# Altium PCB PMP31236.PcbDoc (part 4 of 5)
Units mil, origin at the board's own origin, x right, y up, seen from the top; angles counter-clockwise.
Board outline 6425 x 5322.16 mil, 6 copper layers (Top Layer, Power / GND 1, Signal Layer 1, Signal Layer 2, Power / GND 2, Bottom Layer), stack 78.712 mil thick; 732 components, 346 nets, 1735 pads, 719 vias.
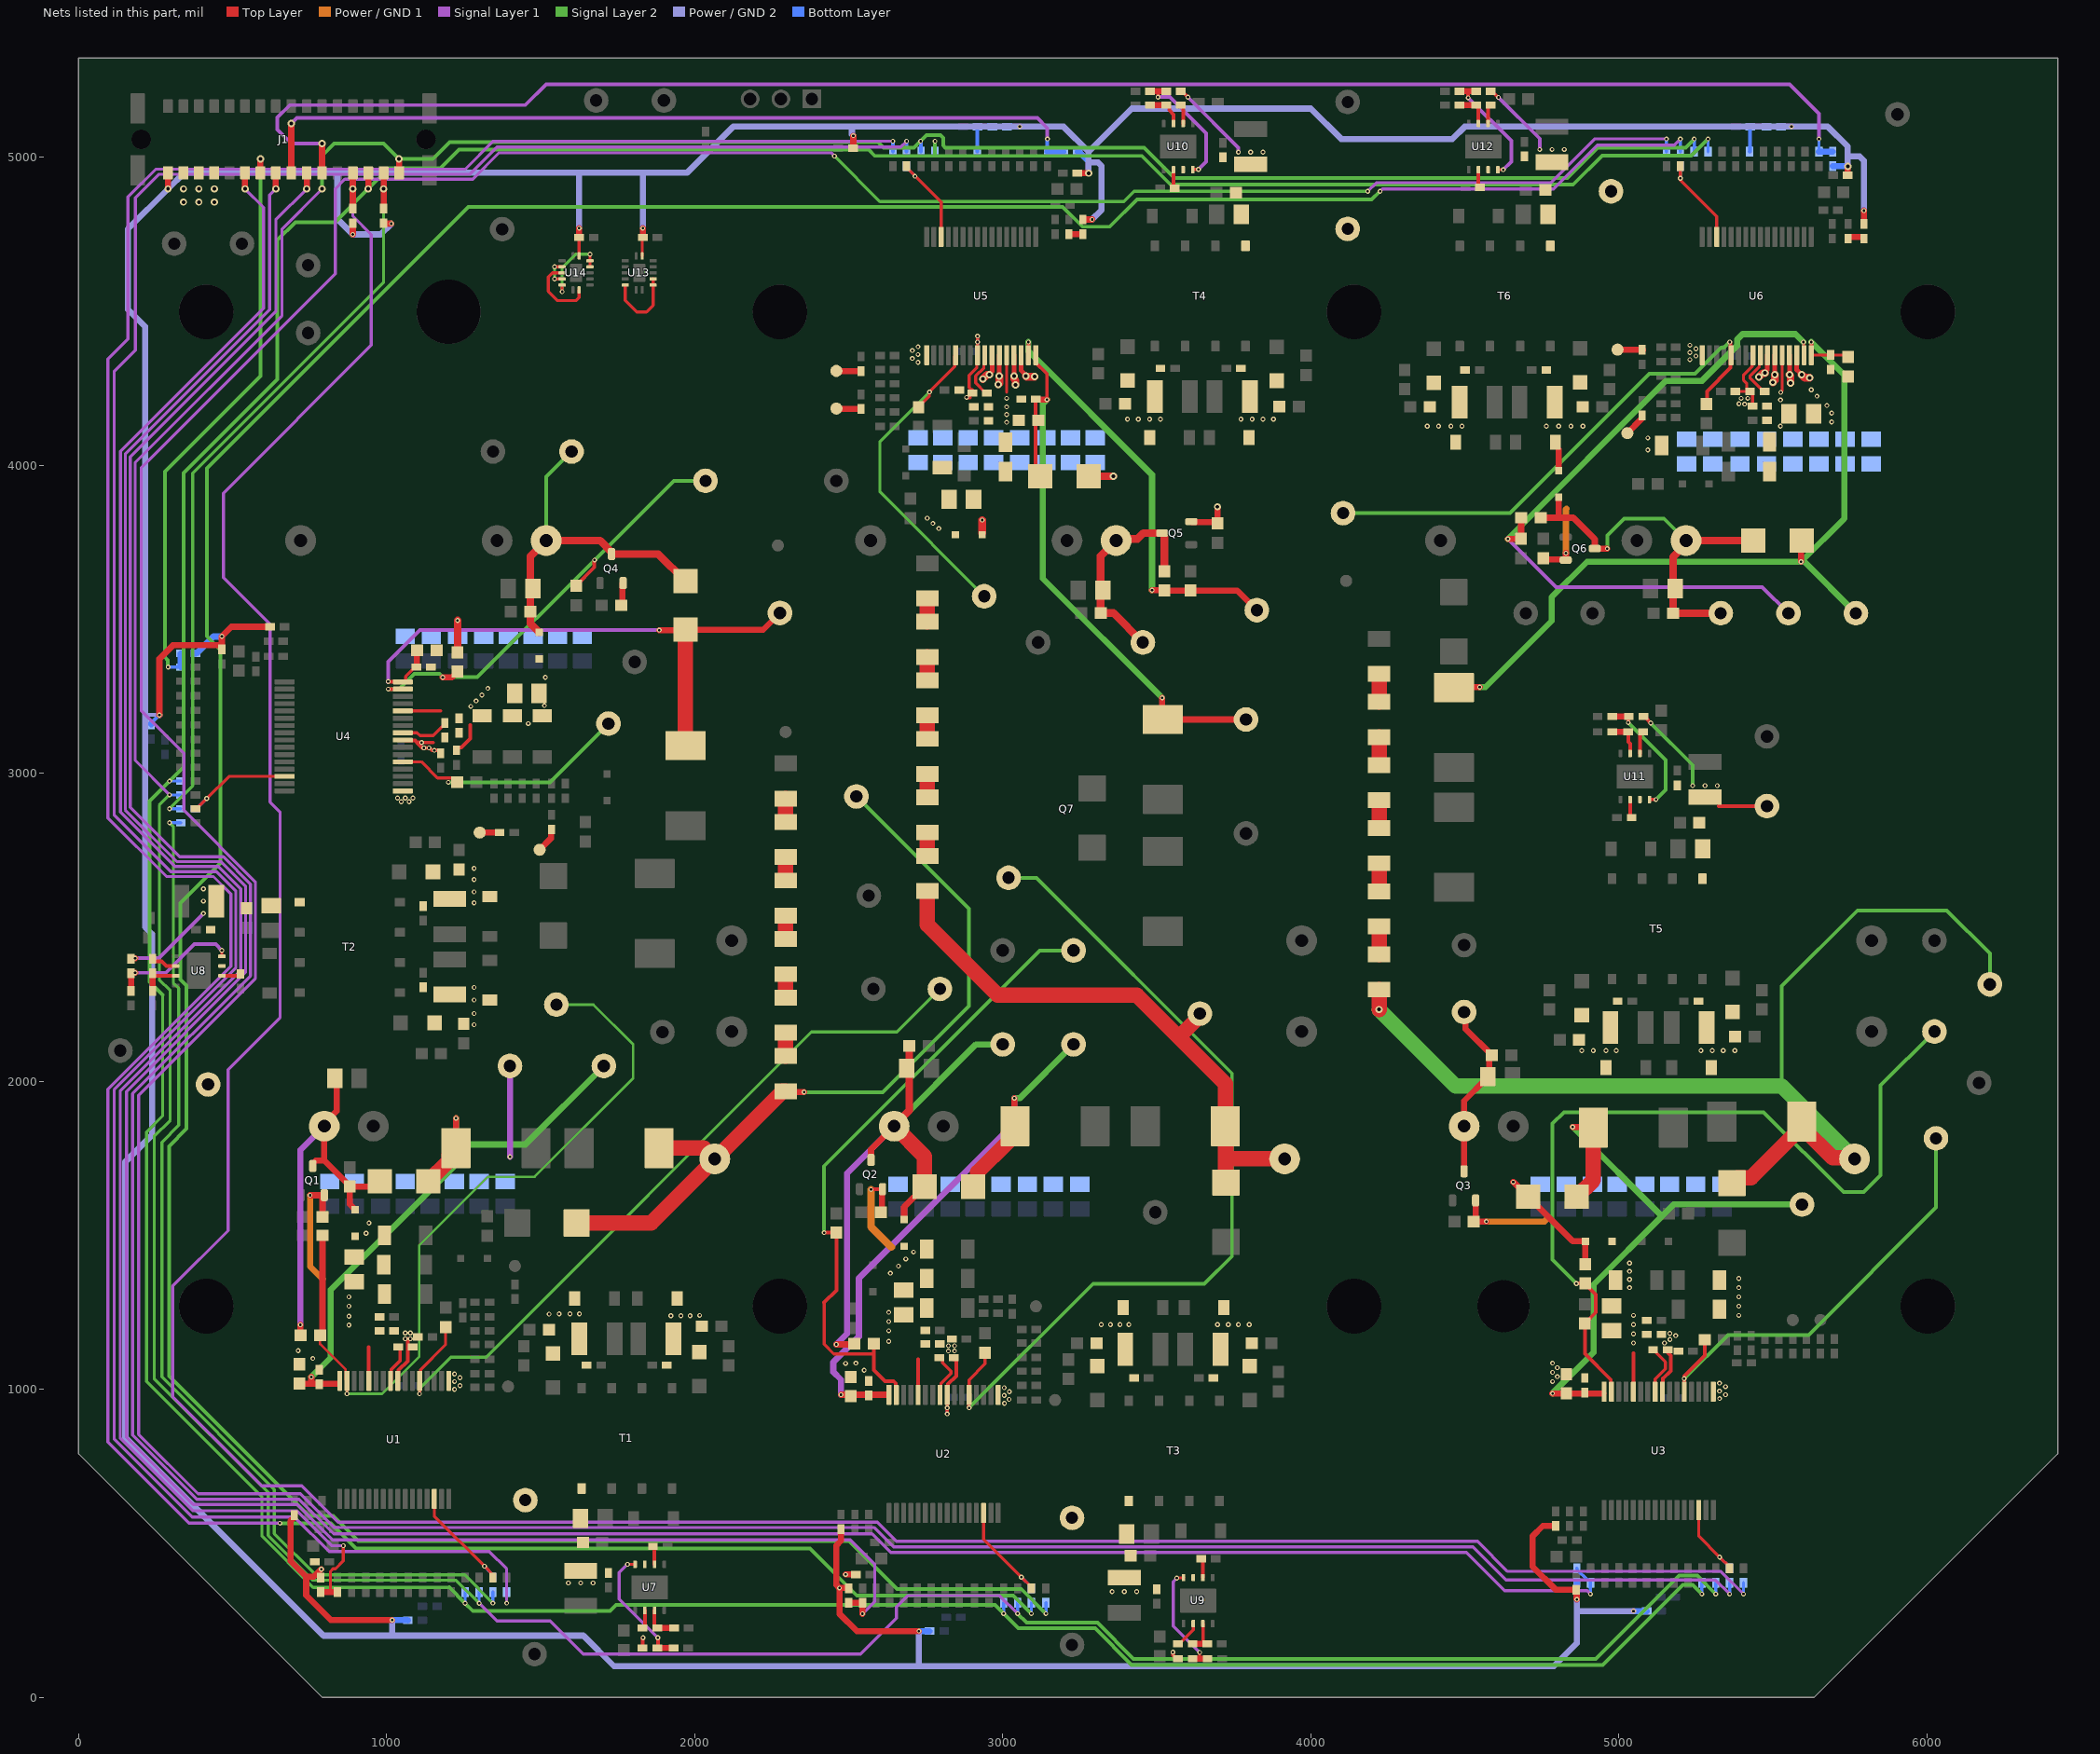
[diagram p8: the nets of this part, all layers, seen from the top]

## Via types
v1: diameter 15.75, hole 7.87, Top Layer to Bottom Layer, tented both sides, 599 vias
v2: diameter 23.62, hole 11.81, Top Layer to Bottom Layer, tented both sides, 92 vias
v3: diameter 19.68, hole 7.87, Top Layer to Bottom Layer, tented both sides, 28 vias

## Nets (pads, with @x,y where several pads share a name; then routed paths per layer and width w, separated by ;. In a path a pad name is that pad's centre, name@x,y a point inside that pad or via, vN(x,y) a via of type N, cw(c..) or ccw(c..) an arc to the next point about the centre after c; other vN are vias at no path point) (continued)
NetR143_2: R143.2 TP42.1 | length 64.4
  Top Layer w20: TP42.1@1301.94,2807.83 R143.2@1366.38,2807.83
NetR146_2: R146.2 TP41.1 | length 81.9
  Top Layer w20: TP41.1@1496.43,2751.93 1533.19,2788.69 1533.19,2812.13 1535,2813.94 R146.2@1535,2817.87
NetR151_1: R151.1 R152.2 | length 75.8
  Top Layer w50: R151.1@2295,2082.09 R152.2@2295,2157.91
NetR152_1: R152.1 R153.2 | length 75.8
  Top Layer w50: R152.1@2295,2272.09 R153.2@2295,2347.91
NetR153_1: R153.1 R154.2 | length 75.8
  Top Layer w50: R153.1@2295,2462.09 R154.2@2295,2537.91
NetR154_1: R154.1 R155.2 | length 75.8
  Top Layer w50: R154.1@2295,2652.09 R155.2@2295,2727.91
NetR155_1: R155.1 R156.2 | length 75.8
  Top Layer w50: R155.1@2295,2842.09 R156.2@2295,2917.91
NetR160_1: R160.1 R168.1 | length 45
  Top Layer w20: R168.1@3215,4751.38 R160.1@3260,4751.38
NetR166_1: R166.1 R167.1 U5.26 | length 94.3
  Top Layer w15: v2(2956.7,4294.73) 2956.7,4297.06 2965.43,4305.79 U5.26@2965.43,4358.07
  Top Layer w25: v2(2935.29,4280.46) 2949.56,4294.73 v2(2956.7,4294.73)
NetR169_1: R169.1 R170.1 U5.27 | length 97.3
  Top Layer w12: U5.27@2989.06,4358.07 U5.27@2989.53,4357.6
  Top Layer w15: v2(2988.96,4289.8) v2(2988.96,4289.8) 2989.01,4358.02 U5.27@2989.06,4358.07
  Top Layer w25: v2(2985.43,4262.98) 2988.96,4266.51 v2(2988.96,4289.8)
NetR174_1: R174.1 R183.1 R187.2 | length 129.5
  Bottom Layer w12: R183.1@2917.76,5018.62 2917.97,5018.84 2917.97,5099.78 R187.2@2918.19,5100
  Bottom Layer w20: R187.2@2918.19,5100 R174.1@2966.18,5100
NetR175_1: R175.1 R176.1 U5.29 | length 98.6
  Top Layer w15: U5.29@3036.3,4358.07 3036.69,4357.68 3036.69,4290.19 v2(3037.08,4289.8)
  Top Layer w25: v2(3037.08,4289.8) 3037.08,4280.61 3041.68,4276.02 v2(3041.68,4261.65)
NetR178_1: R178.1 R180.1 U5.30 | length 103.3
  Top Layer w12: v2(3075.39,4289.8) v2@3075.39,4292.12
  Top Layer w15: U5.30@3059.92,4358.07 3059.92,4307.59 v2@3075.39,4292.12
  Top Layer w25: v2(3075.39,4289.8) 3076.99,4288.19 v2(3103.35,4288.19)
NetR186_2: R186.2 TP53.1 | length 80.6
  Top Layer w20: TP53.1@2460,4184.74 2460.75,4183.98 2539.25,4183.98 R186.2@2540,4183.23
NetR189_2: R189.2 TP52.1 | length 80.1
  Top Layer w20: TP52.1@2460,4306.73 2460.18,4306.55 2539.82,4306.55 R189.2@2540,4306.38
NetR194_1: R194.1 R195.2 | length 75.8
  Top Layer w50: R194.1@2755,2732.09 R195.2@2755,2807.91
NetR195_1: R195.1 R196.2 | length 75.8
  Top Layer w50: R195.1@2755,2922.09 R196.2@2755,2997.91
NetR196_1: R196.1 R197.2 | length 75.8
  Top Layer w50: R196.1@2755,3112.09 R197.2@2755,3187.91
NetR197_1: R197.1 R198.2 | length 75.8
  Top Layer w50: R197.1@2755,3302.09 R198.2@2755,3377.91
NetR198_1: R198.1 R199.2 | length 75.8
  Top Layer w50: R198.1@2755,3492.09 R199.2@2755,3567.91
NetR203_1: R203.1 R211.1 | length 46.2
  Top Layer w20: R211.1@5750,4741.38 R203.1@5796.23,4741.38
NetR209_1: R209.1 R210.1 U6.26 | length 87.2
  Top Layer w15: v2(5475,4300.08) 5475,4302.41 5482.85,4310.27 5482.85,4357.5 U6.26@5483.43,4358.07
  Top Layer w20: v2(5454.6,4287.34) v2@5455.58,4287.34
  Top Layer w25: v2@5455.58,4287.34 5467.63,4299.39 5474.31,4299.39 v2(5475,4300.08)
NetR212_1: R212.1 R213.1 U6.27 | length 91.4
  Top Layer w15: v2(5506.95,4294.5) v2(5506.95,4294.5) 5507,4358.02 U6.27@5507.05,4358.07
  Top Layer w25: v2(5500.19,4269.52) 5506.95,4276.28 v2(5506.95,4294.5)
NetR217_1: R217.1 R226.1 R230.2 | length 135
  Bottom Layer w10: R226.1@5424.89,5018.73 R226.1@5425,5018.62
  Bottom Layer w12: R226.1@5425,5018.62 5426.08,5019.7 5426.08,5098.92 R230.2@5427.15,5100
  Bottom Layer w20: R230.2@5427.15,5100 R217.1@5479.69,5100
NetR218_1: R218.1 R219.1 U6.29 | length 91.9
  Top Layer w15: U6.29@5554.29,4358.07 5554.34,4358.02 5554.34,4294.55 v2(5554.39,4294.5)
  Top Layer w25: v2(5554.39,4294.5) 5557.92,4290.97 v2(5557.92,4267.69)
NetR221_1: R221.1 R223.1 U6.30 | length 100.5
  Top Layer w15: U6.30@5577.91,4358.07 5577.91,4310.25 v2(5593.66,4294.5)
  Top Layer w25: v2(5593.66,4294.5) 5603.65,4284.51 v2(5619.9,4284.51)
NetR229_2: R229.2 TP64.1 | length 77.5
  Top Layer w20: TP64.1@5028.05,4104.82 5074.03,4150.8 5074.03,4160.73 R229.2@5075.84,4162.54
NetR232_2: R232.2 TP63.1 | length 80
  Top Layer w20: TP63.1@4996.23,4375.94 R232.2@5075.15,4375.94
  Top Layer w25: R232.2@5075.15,4375.94 5075.84,4375.26 R232.2@5075.84,4375.12
NetR237_1: R237.1 R238.2 | length 90.8
  Top Layer w50: R237.1@4222.09,2412.17 R238.2@4222.09,2502.99
NetR238_1: R238.1 R239.2 | length 90.8
  Top Layer w50: R238.1@4222.09,2617.17 R239.2@4222.09,2707.99
NetR239_1: R239.1 R240.2 | length 90.7
  Top Layer w50: R239.1@4222.09,2822.17 R240.2@4222.09,2912.91
NetR240_1: R240.1 R241.2 | length 90.9
  Top Layer w50: R240.1@4222.09,3027.09 R241.2@4222.09,3117.99
NetR241_1: R241.1 R242.2 | length 90.8
  Top Layer w50: R241.1@4222.09,3232.17 R242.2@4222.09,3322.99
NetR246_1: R246.1 R250.2 U7.4 | length 412.7
  Top Layer w10: v1(1781.63,431.73) U7.4@1806.48,431.73 ; R246.1@1878.09,160 R246.1@1880.31,162.22
  Top Layer w12: R246.1@1880.31,162.22 v1(1880.31,193.08)
  Top Layer w20: R246.1@1878.09,160 R250.2@1931.38,160
  Signal Layer 1 w10: v1(1781.63,431.73) 1755,405.1 1755,318.4 v1@1879.62,193.78
NetR248_1: R248.1 U7.2 | length 60.4
  Top Layer w12: R248.1@1864.19,489.9 1869.37,484.71 1869.37,431.83 U7.2@1869.47,431.73
NetR249_1: R249.1 R251.2 U7.7 | length 117
  Top Layer w12: U7.7@1869.47,282.13 1869.47,230.81 1875.28,225 R249.1@1878.09,225
  Top Layer w20: R249.1@1878.09,225 R251.2@1932.76,225
NetR249_2: R249.2 U7.6 | length 60.8
  Top Layer w12: R249.2@1830.85,225 1832.16,225 1837.97,230.81 U7.6@1837.97,282.13
NetR254_1: R254.1 R258.2 U8.4 | length 418.4
  Top Layer w10: U8.4@464.8,2405.87 v1(464.8,2425)
  Top Layer w20: R258.2@170,2293.62 R254.1@170,2350.75 171.75,2352.5 v1(183.21,2352.5)
  Signal Layer 1 w12: v1(183.21,2352.5) 282.5,2352.5 375,2445 444.8,2445 v1(464.8,2425)
NetR256_1: R256.1 U8.2 | length 62.6
  Top Layer w12: U8.2@464.8,2342.87 464.9,2342.97 519.35,2342.97 R256.1@525,2348.62
NetR257_1: R257.1 R259.2 U8.7 | length 134.7
  Top Layer w12: R257.1@240,2350.75 240,2348.68 245.81,2342.87 U8.7@315.2,2342.87
  Top Layer w20: R259.2@240,2293.62 R257.1@240,2348.68
NetR257_2: R257.2 U8.6 | length 86.8
  Top Layer w12: R257.2@240,2397.99 240,2394.91 245.81,2389.09 269.81,2389.09 284.54,2374.37 U8.6@315.2,2374.37
NetR262_1: R262.1 R266.2 U9.4 | length 377.8
  Top Layer w10: v1(3565,386.85) 3565.94,387.8 3586.22,387.8 U9.4@3587.13,388.74 ; 3639.41,125 v1(3639.41,145.5)
  Top Layer w20: R262.1@3615.35,125 R262.1@3616.5,125 3639.41,125 R266.2@3665,125 R266.2@3668.1,125
  Signal Layer 1 w10: v1(3565,386.85) 3553.66,375.51 3553.66,231.25 v1(3639.41,145.5)
NetR264_1: R264.1 U9.2 | length 66.6
  Top Layer w12: R264.1@3641.38,450 3644.31,450 3650.12,444.19 U9.2@3650.12,388.74
NetR265_1: R265.1 R267.2 U9.7 | length 99
  Top Layer w10: R267.2@3650.12,173.74 U9.7@3650.12,239.13
  Top Layer w20: R265.1@3616.5,173.74 R267.2@3650.12,173.74
NetR265_2: R265.2 U9.6 | length 88.1
  Top Layer w10: R265.2@3569.25,173.74 3573.19,173.74 3618.62,219.17 U9.6@3618.62,239.13
NetR270_1: R270.1 R274.2 U10.4 | length 421
  Top Layer w10: U10.4@3617.24,4960.2 3617.83,4960.79 3634.92,4960.79 v1(3635.51,4961.38)
  Top Layer w12: v1(3504.21,5195.91) 3504.21,5214.17
  Top Layer w20: R274.2@3478.62,5215 3504.21,5215 ; 3504.21,5214.17 3505.04,5215 R270.1@3530.63,5215
  Signal Layer 1 w12: v1(3504.21,5195.91) 3542.82,5195.91 3659.79,5078.93 3659.79,4985.66 v1(3635.51,4961.38)
NetR272_1: R272.1 U10.2 | length 62.5
  Top Layer w12: R272.1@3548.62,4900 3554.16,4905.54 3554.16,4960.1 U10.2@3554.25,4960.2
NetR273_1: R273.1 R275.2 U10.7 | length 124.3
  Top Layer w12: R273.1@3530.63,5170 3534.57,5170 3540.38,5164.19 3540.38,5153.49 3554.25,5139.61 U10.7@3554.25,5109.8
  Top Layer w20: R275.2@3478.62,5170 R273.1@3530.63,5170
NetR273_2: R273.2 U10.6 | length 64.7
  Top Layer w12: R273.2@3577.87,5170 3579.94,5170 3585.75,5164.19 U10.6@3585.75,5109.8
NetR278_1: R278.1 R282.2 U11.4 | length 407.4
  Top Layer w10: U11.4@5100,2915 v1(5120.98,2915)
  Top Layer w12: v1(5031.1,3164.5) R278.1@5031.1,3183.35
  Top Layer w20: R282.2@4980,3185 R278.1@5032.76,3185 R278.1@5031.1,3183.35
  Signal Layer 2 w12: v1(5031.1,3164.5) 5152.04,3043.57 5152.04,2946.05 v1(5120.98,2915)
NetR280_1: R280.1 U11.2 | length 60.7
  Top Layer w12: U11.2@5037.01,2915 5037.1,2914.91 5037.1,2861.17 R280.1@5041.95,2856.32
NetR281_1: R281.1 R283.2 U11.7 | length 125.6
  Top Layer w12: R281.1@5031.1,3135 5031.1,3102.71 5037.01,3096.8 U11.7@5037.01,3064.61
  Top Layer w20: R283.2@4978.35,3135 R281.1@5031.1,3135
NetR281_2: R281.2 U11.6 | length 76.8
  Top Layer w12: U11.6@5068.5,3064.61 5068.5,3129.09 5074.41,3135 R281.2@5078.35,3135
NetR286_1: R286.1 R290.2 U12.4 | length 393.3
  Top Layer w10: U12.4@4607.52,4960.2 v1(4625,4960.2)
  Top Layer w12: v1(4511.06,5193.78) 4511.06,5215
  Top Layer w20: R290.2@4482.81,5215 4511.06,5215 R286.1@4534.86,5215
  Signal Layer 1 w12: v1(4511.06,5193.78) 4651.25,5053.59 4651.25,4986.45 v1(4625,4960.2)
NetR288_1: R288.1 U12.2 | length 51.2
  Top Layer w12: R288.1@4544.15,4913.34 4544.15,4964.11 U12.2@4544.43,4964.39
NetR289_1: R289.1 R291.2 U12.7 | length 118.5
  Top Layer w12: R289.1@4536.65,5170 4538.72,5170 4544.53,5164.19 U12.7@4544.53,5109.8
  Top Layer w20: R291.2@4482.81,5170 R289.1@4536.65,5170
NetR289_2: R289.2 U12.6 | length 64.7
  Top Layer w12: U12.6@4576.02,5109.8 4576.02,5164.19 4581.83,5170 R289.2@4583.9,5170
NetU13_6: U13.6 U13.9 U13.10 | length 250.4
  Top Layer w10: U13.6@1774.45,4585.63 1774.45,4535.67 1811.89,4498.23 1843.23,4498.23 1865,4520 U13.9@1865,4585.63 U13.10@1865,4605.31
NetU14_3: U14.3 U14.5 | length 88.3
  Top Layer w10: v1(1545,4605.31) U14.5@1569.45,4605.31 ; v1(1545,4644.69) U14.3@1569.45,4644.69
  Signal Layer 2 w10: v1(1545,4605.31) v1(1545,4644.69)
NetU14_4: U14.4 U14.8 | length 238.1
  Top Layer w10: U14.4@1569.45,4625 1538.13,4625 1524.61,4611.49 1524.61,4565.39 1555,4535 1614.57,4535 1624.57,4545 U14.8@1624.57,4569.88
NetU14_6: U14.6 U14.12 U14.13 | length 249.4
  Top Layer w10: v1(1569.45,4563.98) U14.6@1569.45,4585.63 ; U14.12@1660,4644.69 U14.13@1660,4664.37 v1(1660,4686.02)
  Signal Layer 2 w10: v1(1569.45,4563.98) 1569.45,4641.32 1614.15,4686.02 v1(1660,4686.02)
nFLT1_HS_U: J1.b6 R2.1 R8.1 | length 5819.5
  Top Layer w10: 818.35,341.38 817.28,342.44 817.28,408.89 825.68,417.28 833.89,417.28 859.28,442.68 v1(859.28,492.28)
  Top Layer w20: v2(540,4897.83) J1.b6@540,4950 ; R2.1@795,341.38 818.35,341.38 R8.1@840,341.38
  Signal Layer 1 w10: v2(540,4897.83) 600,4837.83 600,4510 135.5,4045.5 135.5,2874.5 312.8,2697.2 453.8,2697.2 525.83,2625.17 525.83,2360.56 135,1969.73 135,841.32 370.41,605.91 707.61,605.91 821.24,492.28 v1(859.28,492.28)
nFLT1_HS_V: J1.b8 R40.1 R46.1 | length 7572
  Top Layer w20: v2(639.84,4897.83) 639.92,4897.91 639.92,4949.92 J1.b8@640,4950 ; R40.1@2500,306.38 R46.1@2545,306.38 v1(2545,271.14)
  Signal Layer 1 w10: v2(639.84,4897.83) 620,4877.99 620,4505 151.4,4036.4 151.4,2881.09 319.39,2713.1 462.66,2713.1 541.73,2634.03 541.73,2353.97 155,1967.24 155,843.81 372.32,626.49 709.52,626.49 824.72,511.29 2505.53,511.29 2584.37,432.45 2584.37,310.51 v1(2545,271.14)
nFLT1_HS_W: J1.b10 R78.1 R84.1 | length 9791.3
  Top Layer w20: J1.b10@740,4950 740.23,4949.77 740.23,4898.06 v2(740.45,4897.83)
  Signal Layer 1 w10: v2(740.45,4897.83) 640,4797.38 640,4500 167.31,4027.31 167.31,2889.5 327.8,2729.01 469.25,2729.01 557.64,2640.62 557.64,2342.64 175,1960 175,851.14 383.19,642.95 715.55,642.95 827.81,530.69 2575.6,530.69 2636.42,469.88 4505.12,469.88 4629.21,345.79 4897.56,345.79 v1(4908.35,335)
  Bottom Layer w10: R78.1@4864.27,418.62 4864.27,414.68 4896.83,382.13 4901.54,382.13 4908.35,375.32 R84.1@4908.35,371.38 v1(4908.35,335)
nFLT1_LS_U: J1.b7 R116.1 R122.1 | length 1913.2
  Top Layer w20: J1.b7@590,4950 v2(590,4995)
  Signal Layer 2 w12: v1(290.22,3345) 289.5,3345.72 289.5,3367.37 280,3376.87 280,3980 590,4290 v2(590,4995)
  Bottom Layer w10: v1(290.22,3345) R122.1@331.38,3345
  Bottom Layer w20: R122.1@331.38,3345 R116.1@331.38,3389.39
nFLT1_LS_V: J1.b9 R159.1 R165.1 | length 2764.3
  Top Layer w20: J1.b9@690,4950 v2(690,5110)
  Signal Layer 1 w12: v2(690,5110) 707.91,5127.91 3112.95,5127.91 3145,5095.85 v1(3145,5060)
  Bottom Layer w12: R165.1@3145,5018.62 v1(3145,5060)
  Bottom Layer w20: R165.1@3145,5018.62 R159.1@3196.38,5018.62
nFLT1_LS_W: J1.b11 R202.1 R208.1 | length 5556
  Top Layer w20: J1.b11@790,4950 v2(790,5045)
  Signal Layer 1 w12: v2(790,5045) 690,5045 645,5090 645,5130 685,5170 1450,5170 1517.42,5237.42 5554.39,5237.42 5650,5141.81 v1(5650,5060)
  Bottom Layer w10: R208.1@5650,5018.62 v1(5650,5060)
  Bottom Layer w20: R208.1@5650,5018.62 R202.1@5695.06,5018.62
SDI_HS_U: C16.1 R31.2 U1.14 | length 382.9
  Top Layer w10: U1.14@1154.39,643.82 1154.39,588.39 v1(1317.09,425.68) C16.1@1349.47,393.31 ; C16.1@1344.47,389.37 C16.1@1344.47,393.31
  Bottom Layer w10: v1(1317.09,425.68) 1337.66,405.12 1337.66,396.18 R31.2@1344.47,389.37
SDI_HS_V: C46.1 R69.2 U2.14 | length 358.2
  Top Layer w10: U2.14@2937.97,598.19 2937.97,512.56 v1(3060.67,389.86) 3092.97,357.56 C46.1@3092.97,353.74
  Bottom Layer w10: v1(3060.67,389.86) 3060.79,389.86 3092.97,357.68 R69.2@3092.97,353.74
SDI_HS_W: C76.1 R107.2 U3.14 | length 280.8
  Top Layer w10: U3.14@5259.92,608.19 5259.92,522.64 v1(5327.56,455) 5360,422.56 C76.1@5360,418.62
  Bottom Layer w10: v1(5327.56,455) 5360,422.56 R107.2@5360,418.62
SDI_LS_U: C106.1 R145.2 U4.14 | length 388.8
  Top Layer w10: C106.1@378.62,2885 382.56,2885 v1(415.71,2918.15) 487.64,2990.08 U4.14@673.07,2990.08
  Bottom Layer w10: R145.2@378.62,2885 382.56,2885 v1(415.71,2918.15)
SDI_LS_V: C136.1 R188.2 U5.14 | length 320.6
  Top Layer w10: C136.1@2687.76,4971.38 2687.76,4967.44 2715,4940.2 v1(2715,4938.82) 2716.38,4938.82 2800.08,4855.12 U5.14@2800.08,4741.93
  Bottom Layer w10: R188.2@2687.76,4971.38 2687.76,4967.44 2715,4940.2 v1(2715,4938.82)
SDI_LS_W: C166.1 R231.2 U6.14 | length 317.1
  Top Layer w10: C166.1@5200,4971.38 v1(5200,4932.59) 5200,4926.69 5318.07,4808.62 U6.14@5318.07,4741.93
  Bottom Layer w10: v1(5200,4932.59) R231.2@5200,4971.38
SDO_HS_U: R34.1 R188.1 | length 8683
  Signal Layer 1 w10: v1(1389.47,305.82) 1389.47,416.56 1333.1,472.93 812.72,472.93 700.65,585 368.82,585 115,838.82 115,1972.22 509.92,2367.15 509.92,2618.58 447.21,2681.29 298.71,2681.29 115,2865 115,4305 184.21,4374.21 184.21,4869.21 260,4945 1269.41,4945 1358.17,5033.76 2668.98,5033.76 v1(2687.76,5052.54)
  Bottom Layer w10: v1(1389.47,305.82) R34.1@1389.47,342.13
  Bottom Layer w12: R188.1@2687.76,5018.62 v1(2687.76,5052.54)
SDO_HS_V: R72.1 R231.1 | length 11575.5
  Signal Layer 1 w10: v1(4225,4890) 4232.83,4897.83 4788.6,4897.83 4930.82,5040.05 5180.05,5040.05 v1(5200,5060)
  Signal Layer 2 w12: v1(3140.22,271.38) 3060.37,351.22 2656.97,351.22 2501.15,507.03 907.97,507.03 826.43,588.57 747.44,588.57 293.57,1042.44 293.57,1789.45 350,1845.88 350,2310.5 330.5,2330 330.5,2578.48 460.23,2708.2 460.23,3400.48 415.71,3445 415.71,3990.71 1265,4840 3195,4840 3260,4775 3347.73,4775 3435.79,4863.06 4198.06,4863.06 v1(4225,4890)
  Bottom Layer w10: v1(3140.22,271.38) R72.1@3140.22,306.5 ; R231.1@5200,5018.62 v1(5200,5060)
SDO_LS_U: R31.1 R147.1 | length 3370.8
  Signal Layer 2 w10: v1(295,2840) 307.21,2827.79 307.21,2319.7 325,2301.91 325,1857.32 270,1802.32 270,1040 635,675 635,570.96 634.82,570.79 634.82,531.42 769.03,397.22 1253.07,397.22 v1(1344.47,305.82)
  Bottom Layer w10: v1(295,2840) R147.1@331.38,2840 ; v1(1344.47,305.82) R31.1@1344.47,342.13
SDO_LS_V: R69.1 R190.1 | length 10345.6
  Signal Layer 1 w10: v1(653.6,565.12) 358.38,565.12 95,828.5 95,1974.72 494.02,2373.73 494.02,2608.42 437.44,2665 285,2665 95,2855 95,4345 160,4410 160,4871.42 250.49,4961.91 1255,4961.91 1344.76,5051.66 2522.78,5051.66 2523.65,5052.54 v1(2643.15,5052.54)
  Signal Layer 2 w12: v1(653.6,565.12) 818.12,565.12 900.56,482.69 2373.75,482.69 2526.32,330.12 3034.23,330.12 v1(3092.97,271.38)
  Bottom Layer w10: v1(3092.97,271.38) R69.1@3092.97,306.5
  Bottom Layer w12: R190.1@2643.15,5018.62 v1(2643.15,5052.54)
SDO_LS_W: R107.1 R233.1 | length 14593.3
  Signal Layer 1 w10: v1(2453.5,5004.41) 2442.91,5015 1365,5015 1279.09,4929.09 864.09,4929.09 832.84,4897.84 832.84,4622.16 202.99,3992.3 202.99,3203.23 341.22,3065 341.22,2880.07 573.54,2647.74 573.54,2333.54 195,1955 195,853.64 387.51,661.13 719.87,661.13 830.02,550.98 2583.11,550.98 2645.82,488.27 4527.2,488.27 4634.25,381.22 5313.78,381.22 v1(5360,335) ; v1(4185,4890) 4212.95,4917.95 4779,4917.95 4921.05,5060 v1(5155,5060)
  Signal Layer 2 w10: v1(2453.5,5004.41) 2601,4856.91 3393.04,4856.91 3426.13,4890 v1(4185,4890)
  Bottom Layer w10: R233.1@5155,5018.62 v1(5155,5060) ; v1(5360,335) R107.1@5360,371.38
SPI_CS: J1.b16 R35.1 R73.1 R111.1 R148.1 R191.1 R234.1 | length 15093.8
  Top Layer w20: J1.b16@1040,4950 v2(1040,4995)
  Signal Layer 1 w10: v1(295,2930) 183.21,3041.79 183.21,4009.81 660,4486.6 660,4767.83 v2(790,4897.83) ; v1(1300.21,305) 1357.8,247.42 1530.35,247.42 1637.77,140 2538.27,140 2654.65,256.38 2654.65,292.82 2691.95,330.12 2989.31,330.12 v1(3048.05,271.38)
  Signal Layer 2 w10: v1(295,2930) 261.65,2896.65 261.65,2330 296.91,2294.75 296.91,1873.48 245,1821.57 245,1035 615.05,664.95 615.05,525.37 760.35,380.08 1225.14,380.08 v1(1300.21,305)
  Signal Layer 2 w12: v2(790,4897.83) 790,5005 830,5045 990,5045 v2(1040,4995) 1150,4995 1205,5050 2595,5050 2613.5,5031.5 2710.99,5031.5 2732.02,5052.54 v1(2733.04,5052.54) 2752.82,5072.31 2797.68,5072.31 2806.38,5063.62 2806.38,5038.53 2813.41,5031.5 3458.62,5031.5 3557.52,4932.59 4832.42,4932.59 4931.33,5031.5 5217.51,5031.5 5245,5058.99 v1(5245,5060) ; v1(3048.05,271.38) 3077.3,242.13 3307.87,242.13 3425,125 4925.67,125 5195.67,395 5255,395 v1(5315,335)
  Bottom Layer w10: v1(295,2930) R148.1@331.38,2930 ; R35.1@1299.47,342.13 1299.84,341.75 1299.84,305.37 v1(1300.21,305) ; v1(3048.05,271.38) R73.1@3048.05,306.5 ; R234.1@5245,5018.62 v1(5245,5060) ; v1(5315,335) R111.1@5315,371.38
  Bottom Layer w12: v1(2733.04,5052.54) 2733.04,5051.52 2735,5049.56 R191.1@2735,5018.62
SPI_MISO: J1.b13 R110.1 R294.1 | length 9884.9
  Top Layer w20: R294.1@889.84,4833.62 889.92,4833.7 889.92,4949.92 J1.b13@890,4950
  Signal Layer 1 w10: v2(889.84,4897.83) 889.84,4810.16 950,4750 950,4390 470,3910 470,3635 621.38,3483.62 621.38,2907.04 653.54,2874.88 653.54,2206.38 485,2037.84 485,1515 305,1335 305,975 593.86,686.14 724.79,686.14 842.74,568.19 2592.86,568.19 2654.83,506.22 4541.81,506.22 4639.25,408.78 5331.22,408.78 v1(5405,335)
  Bottom Layer w10: v1(5405,335) R110.1@5405,371.38
SPI_MOSI: J1.b15 R145.1 R295.2 | length 2453.5
  Top Layer w20: R295.2@990,4833.62 v2(990,4897.83) J1.b15@990,4950
  Signal Layer 2 w10: v1(295,2885) 370,2960 370,3975 990,4595 v2(990,4897.83)
  Bottom Layer w10: v1(295,2885) R145.1@331.38,2885
SPI_SCLK: J1.b14 R28.1 R66.1 R104.1 R142.1 R185.1 R228.1 | length 14754.6
  Top Layer w20: v2(940,4897.83) J1.b14@940,4950
  Signal Layer 2 w10: 272.49,2280.85 272.49,1887.49 220,1835 220,1025 595,650 595,522.93 761.01,356.93 1202.54,356.93
  Signal Layer 2 w12: 272.49,2280.85 230,2323.35 230,2910 v1(295,2975) 295,2975.35 340,3020.35 340,3975 645,4280 645,4731.6 703.4,4790 832.17,4790 v2(940,4897.83) 1007.17,4965 1175,4965 1235,5025 2565,5025 2585,5005 2780,5005 ; 1202.54,356.93 v1(1254.47,305) 1279.47,280 1725,280 1745,300 2974.43,300 v1(3003.05,271.38) 3050.21,224.22 3299.68,224.22 3418.89,105.02 4948.37,105.02 5208.35,365 5240,365 v1(5270,335) ; v1(2780,5052.54) 2780,5005 ; v1(5290,5060) 5235.87,5005.87 4945.87,5005.87 4852.02,4912.02 3544.63,4912.02 3451.65,5005 2780,5005
  Bottom Layer w10: v1(295,2975) R142.1@331.38,2975 ; v1(1254.47,305) R28.1@1254.47,342.13 ; v1(3003.05,271.38) R66.1@3003.05,306.5 ; v1(5270,335) R104.1@5270,371.38 ; R228.1@5290,5018.62 v1(5290,5060)
  Bottom Layer w12: R185.1@2780,5018.62 v1(2780,5052.54)
VCC2H_U: C9.2 C24.1 C25.1 C26.1 C27.1 C181.1 C182.1 C183.1 D6.1 D37.1 D38.1 U1.24 | length 149.4
  Top Layer w12: U1.24@1036.28,1027.68 1038.35,1029.75 1038.35,1062.38 1067.82,1091.85 1067.82,1164.06
  other v1: 1059.9,1163.9 1077,1163.9 1059.9,1182.8 1077,1182.8 1527.22,1244.28 1560,1245 1595,1245 1625.67,1245 933.14,1506.47 942.56,1540
VCC2H_V: C39.2 C54.1 C55.1 C56.1 C57.1 C201.1 C202.1 C203.1 D12.1 D47.1 D48.1 U2.24 | length 244.3
  Top Layer w10: v1(2661.47,1399.86) v1@2661.69,1399.86 ; v1@2684.78,1422.95 v1(2685,1422.95) v1@2685,1424.51
  Top Layer w12: v1(2819.86,920) v1(2819.86,939.72) U2.24@2819.86,982.05 2821.93,984.12 2821.93,1016.75 2848.75,1043.56 2848.75,1096.94 2847.94,1097.76 C39.2@2840.18,1097.76
  Signal Layer 1 w12: v1(2819.86,920) v1(2819.86,939.72) 2819.86,964.5
  other v1: 2823.59,1124.41 2843.66,1124.21 2823.59,1141.28 2843.66,1141.28 3319.91,1210.19 3350,1210.19 3380.62,1210.19 3409.59,1210 2635.48,1376.98 2710.5,1445.83
VCC2H_W: C69.2 C84.1 C85.1 C86.1 C87.1 C221.1 C222.1 C223.1 D18.1 D57.1 D58.1 U3.24 | length 140.1
  Top Layer w12: U3.24@5141.81,992.05 5143.88,994.12 5143.88,1034.66 5168.39,1059.17 5168.39,1109.73 C69.2@5160.31,1117.81
  other v1: 5148.83,1150.28 5166.21,1161.65 5184.72,1174.29 5165.96,1181.5 5034.87,1330 5034.87,1357.04 5034.87,1382.96 5034.87,1410 5267.01,2100 5303.5,2100 5339.19,2100 5377.01,2100
VCC2L_U: C99.2 C114.1 C115.1 C116.1 C117.1 C191.1 C192.1 C193.1 D24.1 D42.1 D43.1 U4.24 | length 186.3
  Top Layer w12: U4.24@1056.93,3108.19 1059,3106.12 1092.88,3106.12 1100.64,3098.36 1115.79,3083.21 1120.67,3083.21 1121.39,3082.5 v1(1137.67,3082.5) 1138.69,3082.5 1146.44,3074.75 1169.19,3074.75 1175,3068.94 C115.1@1175,3065 ; 1103,3100.72 1112.67,3100.72 v1(1113.39,3100) 1150.77,3100
  other v1: 1283.55,2579.18 1283.55,2615 1283.55,2655 1283.55,2691.7 1154.5,3074.75 1120.67,3082.5 1459.42,3161.46 1512,3220 1515,3312.01
VCC2L_V: C129.2 C144.1 C145.1 C146.1 C147.1 C211.1 C212.1 C213.1 D30.1 D52.1 D53.1 U5.24 | length 243.5
  Top Layer w10: C129.2@2901.38,4245 2899.13,4245 2891.14,4253 2891.14,4292.14 2915.87,4316.87 2915.87,4355.75 U5.24@2918.19,4358.07
  Top Layer w12: v1(2882.71,4220.84) 2883.04,4220.5 2893.5,4220.5 ; U5.24@2918.19,4358.07 v1(2918.19,4400.39) v1(2918.19,4420)
  Signal Layer 1 w12: 2918.19,4379.23 v1(2918.19,4400.39) v1(2918.19,4420)
  other v1: 2792.52,3795 2773.39,3811.5 2755,3828.5 3773.62,4150 3810,4150 3845,4150 3879.27,4150
VCC2L_W: C159.2 C174.1 C175.1 C176.1 C177.1 C231.1 C232.1 C233.1 D36.1 D62.1 D63.1 U6.24 | length 302.7
  Top Layer w10: C175.1@5378.94,4240 5425.53,4240 C159.2@5426.18,4240 ; C159.2@5422.24,4240 5415.43,4246.81 5415.43,4267.31 5404.84,4277.9 5404.84,4292.91 5433.11,4321.18 5433.11,4355 U6.24@5436.18,4358.07 ; C159.2@5427.3,4240 5434.11,4233.19 C176.1@5434.11,4192.5
  Top Layer w20: D36.1@4805,3985 D63.1@4805,4051.9
  other v1: 5094.47,4050 5094.47,4089.06 4765,4127.47 4805,4127.47 4845,4127.47 4883.5,4127.47 5691.18,4141.09 5691.18,4169.71 5675.77,4194.31 5409.1,4198.86 5390.29,4199.74 5397.44,4217.85 5419.08,4217.85
VceclpH_U: C8.2 D3.2 D5.2 R6.1 TP2.1 U1.32 | length 2023.3
  Top Layer w10: U1.32@844.23,1018.5 847.3,1021.57 U1.32@847.3,1027.68
  Top Layer w20: R6.1@716.93,1018.5 759.27,1018.5 ; v1(755.33,1039.93) 755.33,1022.44 759.27,1018.5 ; U1.32@844.23,1018.5 759.27,1018.5 ; D3.2@1225,1783.31 v1(1225,1880)
  Top Layer w50: D5.2@1135.12,1675 1202.83,1742.72 1202.83,1761.14 D3.2@1225,1783.31
  Signal Layer 2 w20: v1(755.33,1039.93) 818.18,1102.78 818.18,1322.88 1225,1729.7 1225,1795 ; v1(1225,1880) 1225,1795 ; TP2.1@1705,2050 1450,1795 1225,1795
VceclpH_V: C38.2 D9.2 D11.2 R44.1 TP13.1 U2.32 | length 1978.8
  Top Layer w20: v1(2475,982.46) U2.32@2628,982.46 ; v1(3037.5,1945) 3037.5,1857.11 D9.2@3040.08,1854.53
  Top Layer w50: D11.2@2903.74,1658 2918.11,1672.37 2918.11,1704.74 3017.83,1804.47 3017.83,1832.28 D9.2@3040.08,1854.53
  Signal Layer 1 w20: v1(2475,982.46) 2475,1031.36 2450,1056.36 2450,1088.04 2533.22,1171.26 2533.22,1360.59 3037.5,1864.87 v1(3037.5,1945)
  Signal Layer 2 w20: v1(3037.5,1945) 3055,1945 TP13.1@3230,2120
VceclpH_W: C68.2 D15.2 D17.2 R82.1 TP23.1 U3.32 | length 2092.1
  Top Layer w12: U3.32@4950.76,986.69 4952.83,988.76 U3.32@4952.83,992.05
  Top Layer w20: v1@4784.42,986.69 4888.19,986.69 4890,988.5 C68.2@4890,989.57 ; v1(4850.31,1851.81) 4915.12,1851.81 D15.2@4917.4,1849.53 ; C68.2@4890,986.69 U3.32@4950.76,986.69
  Top Layer w50: D17.2@4863.74,1625 4917.4,1678.66 D15.2@4917.4,1849.53
  Signal Layer 2 w20: v1(4785,986.69) 4918.54,1120.24 4918.54,1340.21 5140.23,1561.9 ; v1(4850.31,1851.81) 5140.23,1561.9 ; TP23.1@5595,1600 5178.33,1600 5140.23,1561.9
VceclpL_U: C98.2 D21.2 D23.2 R120.1 TP33.1 U4.32 | length 1954
  Top Layer w10: U4.32@1056.93,3297.17 1058.75,3297.17 1061.82,3300.24 1061.82,3314.38 1092.44,3345 C98.2@1096.38,3345
  Top Layer w12: v1(1005,3297.91) 1005.37,3297.54 1056.56,3297.54 U4.32@1056.93,3297.17
  Top Layer w20: C98.2@1096.38,3345 1097.44,3346.06 1097.44,3398.94 R120.1@1098.5,3400 ; v1(1885,3465) 1968.74,3465 D23.2@1970,3466.26 2222.13,3466.26 TP33.1@2276.77,3520.91
  Top Layer w50: D21.2@1970,3089.92 D23.2@1970,3466.26
  Signal Layer 1 w12: v1(1005,3297.91) 1005,3362.6 1107.4,3465 v1(1885,3465)
VceclpL_V: C128.2 D27.2 D29.2 R163.1 TP44.1 U5.32 | length 1928.5
  Top Layer w12: C128.2@3107.17,4215 3107.17,4146.38 3107.17,3979.09 D29.2@3121.26,3965 ; U5.32@3107.17,4358.07 3107.17,4333.66 3143.62,4297.2 v1(3143.62,4213.19)
  Top Layer w20: C128.2@3107.17,4215 3108.98,4213.19 v1(3143.62,4213.19) ; v1(3517.76,3245) 3517.76,3177.17 D27.2@3520,3174.92 TP44.1@3790,3174.92
  Signal Layer 2 w20: v1(3143.62,4213.19) 3130,4199.57 3130,3632.76 v1(3517.76,3245)
VceclpL_W: C158.2 D33.2 D35.2 R206.1 TP55.1 U6.32 | length 2639.1
  Top Layer w10: U6.32@5625.16,4358.07 5738.43,4358.07 R206.1@5745,4351.5
  Top Layer w12: U6.32@5625.16,4358.07 U6.32@5625.16,4358.07 5625.24,4400.31 v1(5625.31,4400.39)
  Top Layer w20: D33.2@4465,3278.54 4466.46,3280 v1(4548.62,3280) ; v1(5592.13,3687.2) 5592.13,3754.57 D35.2@5593.66,3756.1
  Signal Layer 2 w20: v1(4548.62,3280) 4567.4,3280 4782.4,3495 4782.4,3572.4 4897.2,3687.2 v1(5592.13,3687.2) ; v1(5625.31,4400.39) 5732.46,4293.25 5732.46,3827.53 v1(5592.13,3687.2) ; TP55.1@5770,3520 5602.8,3687.2 v1(5592.13,3687.2)
VclampH_U: R21.1 R24.2 TP1.1 U1.31 | length 2532.5
  Top Layer w8: R21.1@783.43,1175.81 783.43,1147.5 866.85,1064.07 866.85,1031.75 U1.31@870.93,1027.68 v1(870.93,985.35)
  Top Layer w20: R21.1@783.43,1175.81 791.5,1183.88 R24.2@791.5,1500
  Signal Layer 2 w8: v1(870.93,985.35) 985.04,985.35 1105.92,1106.23 1105.92,1467.77 1328.09,1689.95 1480.59,1689.95 1800,2009.36 1800,2120 1671.03,2248.97 TP1.1@1550.78,2248.97
VclampH_V: R59.1 R62.2 TP12.1 U2.31 | length 2122.1
  Top Layer w10: 2420,1281.66 2420,1145.94 2451.38,1114.57 2581.06,1114.57
  Top Layer w12: 2420,1281.66 2460,1321.66 R62.2@2460,1508.5 v1(2420,1508.5) ; R59.1@2581.06,1148.03 2581.06,1114.57 2581.06,1062.85 2617.48,1026.43 2645.41,1026.43 2652.44,1019.4 2652.44,984.12 U2.31@2654.51,982.05
  Signal Layer 2 w12: v1(2420,1508.5) 2420,1724.52 3120.48,2425 TP12.1@3230,2425
VclampH_W: R97.1 R100.2 TP22.1 U3.31 | length 2745.6
  Top Layer w12: v1(4862.26,1343.5) R97.1@4890.81,1343.5 4890.81,1342.52 4925,1308.33 4925,1249.49 4890,1214.49 R100.2@4890,1213.5 4890,1115.53 4974.53,1030.99 4974.53,993.97 U3.31@4976.46,992.05
  Signal Layer 2 w12: v1(4862.26,1343.5) 4785,1420.77 4785,1862.48 4822.52,1900 5470,1900 5730,1640 5795,1640 5850,1695 5850,1986.61 TP22.1@6025,2161.61
VclampL_U: R136.1 R139.2 TP32.1 U4.31 | length 1536.3
  Top Layer w12: v1(1005,3273.54) U4.31@1056.93,3273.54 ; R139.2@1615,3608.74 1615,3609.72 1674.28,3669.01 1674.28,3691.84 v1(1675,3692.56)
  Top Layer w20: v1(1182.01,3312.01) 1211.82,3312.01 1220.31,3320.51 1221.3,3320.51 1230,3329.21 R136.1@1230,3330.2
  Signal Layer 2 w12: v1(1005,3273.54) 1039.11,3273.54 1088.91,3323.35 1170.68,3323.35 v1(1182.01,3312.01) 1294.45,3312.01 v1(1675,3692.56) 1932.44,3950 TP32.1@2035,3950
VclampL_V: R179.1 R182.2 TP43.1 U5.31 | length 1380.9
  Top Layer w12: U5.31@3083.54,4358.07 v1(3083.54,4400.39)
  Top Layer w20: v1(3485,3595) 3523.5,3595 R179.1@3525,3593.5 R182.2@3610,3593.5 3761.5,3593.5 TP43.1@3825,3530
  Signal Layer 2 w20: v1(3083.54,4400.39) 3083.54,4371.19 3485,3969.73 v1(3485,3595)
VclampL_W: R222.1 R225.2 TP54.1 U6.31 | length 2423.4
  Top Layer w10: v1(5599.41,4400.39) 5600.47,4399.33 5600.47,4359.13 U6.31@5601.54,4358.07
  Top Layer w20: v1(4640,3761.5) R225.2@4682.76,3761.5 4683.13,3761.87 4683.13,3829.63 R222.1@4683.5,3830
  Signal Layer 1 w12: v1(4640,3761.5) 4796.5,3605 5466.18,3605 TP54.1@5551.18,3520
  Signal Layer 2 w20: v1(4640,3761.5) 5153.22,4274.72 5270.62,4274.72 5384.04,4388.14 5384.04,4408.51 5401.83,4426.3 5573.5,4426.3 v1(5599.41,4400.39)
VcpH_U: C9.1 U1.25 | length 119.5
  Top Layer w12: U1.25@1012.66,1027.68 1014.73,1029.75 1014.73,1064.08 1043.39,1092.74 C9.1@1043.39,1134.41
VcpH_V: C39.1 U2.25 | length 159.5
  Top Layer w10: C39.1@2787.93,1102.76 2797.93,1102.76 2804.75,1095.94 2804.75,1085.94 2813.14,1077.55 2831.84,1058.85 2831.84,1050.56 2799.31,1018.04 2799.31,985.12 U2.25@2796.24,982.05
VcpH_W: C69.1 U3.25 | length 169.3
  Top Layer w10: C69.1@5111.38,1128.62 5115.32,1128.62 5122.13,1121.81 5122.13,1117.87 5151.48,1088.52 5151.48,1066.17 5118.19,1032.87 U3.25@5118.19,992.05
VcpL_U: C99.1 U4.25 | length 154.8
  Top Layer w10: U4.25@1056.93,3131.81 1098.5,3131.81 1108.03,3122.28 1150.67,3122.28 1188.5,3160.12 C99.1@1188.5,3163.7
VcpL_V: C129.1 U5.25 | length 153
  Top Layer w10: U5.25@2941.81,4358.07 2938.74,4355 2938.74,4317.01 2911.88,4290.15 2911.88,4267.8 2944.68,4235 C129.1@2948.62,4235
VcpL_W: C159.1 U6.25 | length 156.2
  Top Layer w10: U6.25@5457.73,4356 5456.73,4355 5456.73,4321.59 5426.45,4291.32 5426.45,4283.03 C159.1@5462.68,4246.81 ; C159.1@5469.49,4240 C159.1@5473.43,4240
  Top Layer w12: U6.25@5457.73,4356 U6.25@5459.8,4358.07 ; C159.1@5463.68,4245.81 5469.49,4240 C159.1@5473.43,4240
VEE2H_U: C8.1 C26.2 C27.2 C28.2 C29.2 C30.2 C187.2 C188.2 C189.2 D40.2 D41.2 Q1.2 R6.2 R27.1 U1.17 U1.28 | length 506.2
  Top Layer w12: U1.28@941.79,1027.68 941.79,1136.88
  Top Layer w20: v1(750.9,1630) 786.46,1630 791.5,1624.96 R27.1@791.5,1560 R27.1@790.51,1560
  Power / GND 1 w20: v1(750.9,1630) 750.9,1399.07 791.5,1358.47
  other v1: 1220,1000 1237.92,1012.06 1220,1025 1237.92,1037.85 1220,1050 760,1100 712.44,1125.32 877.5,1208.42 877.5,1237.43 1922.33,1238.7 1955,1238.7 1985,1238.7 2015.84,1240 877.5,1270 877.5,1300
VEE2H_V: C38.1 C56.2 C57.2 C58.2 C59.2 C60.2 C207.2 C208.2 C209.2 D50.2 D51.2 Q2.2 R44.2 R65.1 U2.17 U2.28 | length 440.7
  Top Layer w12: v1(2572.4,1648.5) 2573.12,1649.22 2606.97,1649.22 Q2.2@2607.99,1648.19 ; U2.28@2725.37,982.05 2725.37,1097.76
  Top Layer w20: R65.1@2603.9,1575 2607.99,1579.09 Q2.2@2607.99,1648.19
  Power / GND 1 w25: v1(2572.4,1648.5) 2572.4,1527.63 2638.13,1461.9
  other v1: 3005.61,954.4 3020.65,967.35 3005,980 3021.59,992.52 3005,1005 2550,1061.93 2490,1084.04 2523.5,1085.01 2630.05,1155.84 2630,1190 3697.33,1210.19 3732.52,1210.19 3765,1210.19 3800.14,1210.19 2630,1220 2630,1250
VEE2H_W: C68.1 C86.2 C87.2 C88.2 C89.2 C90.2 C227.2 C228.2 C229.2 D60.2 D61.2 Q3.2 R82.2 R103.1 U3.17 U3.28 | length 422.5
  Top Layer w12: U3.28@5047.32,992.05 5047.32,1116.38
  Top Layer w20: Q3.2@4535.43,1613.31 4535.43,1548.78 4539.21,1545 v1(4570,1545)
  Power / GND 1 w20: v1(4570,1545) 4759,1545 4765,1551
  other v1: 5327.56,970 5346.56,982.29 5326.85,994.12 5346.56,1008.4 5326.85,1020 4785,1025 4800.6,1041.17 4785,1055 4800.6,1070.21 4785,1085 5047.82,1150.47 5048,1180 5048,1210 5048,1240 5390,1240 5390,1270 5390,1300 5390,1330 5390,1360 4880,2100 4917.4,2100 4958.54,2100 4992.01,2100
VEE2L_U: C98.1 C116.2 C117.2 C118.2 C119.2 C120.2 C197.2 C198.2 C199.2 D45.2 D46.2 R120.2 U4.17 U4.28 | length 228.7
  Top Layer w10: U4.28@1051.93,3202.68 1174.72,3202.68
  Top Layer w12: C119.2@1226.5,3075 1226.5,3078.94 1232.31,3084.75 1242.2,3084.75 1270.63,3113.18 1270.63,3156.82
  other v1: 1283.55,2183.78 1283.55,2220 1283.55,2264.15 1283.55,2305 1047.22,2907.6 1072.55,2907.6 1035,2920 1060,2920 1085,2920 1272.85,3217.69 1290,3235 1308.92,3254.39 1328.31,3276.12
VEE2L_V: C128.1 C146.2 C147.2 C148.2 C149.2 C150.2 C217.2 C218.2 C219.2 D55.2 D56.2 Q5.2 R163.2 R184.1 U5.17 U5.28 | length 253.5
  Top Layer w10: 3012.68,4237.82 U5.28@3012.68,4358.07
  Top Layer w20: Q5.2@3612.24,3817.4 3614.06,3815.59 3693.07,3815.59 3697.17,3819.68 v2(3697.17,3865.6)
  other v1: 3012.68,4140 3405,4150 3440,4150 3476.91,4150 3512.01,4150 3012.68,4165 3012.68,4190 3012.68,4217.74 2725,4335 2706.11,4347.26 2725,4360 2706.11,4372.85 2725,4385
VEE2L_W: C158.1 C176.2 C177.2 C178.2 C179.2 C180.2 C237.2 C238.2 C239.2 D65.2 D66.2 Q6.2 R206.2 R227.1 U6.17 U6.28 | length 360.8
  Top Layer w10: v1@5530.67,4242.71 U6.28@5530.67,4358.07
  Top Layer w20: R227.1@4755,3698.5 4759.09,3694.41 4825.94,3694.41 Q6.2@4827.76,3692.6 4828.58,3691.77 v1(4828.58,3715)
  Power / GND 1 w20: v1(4828.58,3715) 4828.58,3857.45 4830.94,3859.81
  other v1: 4378.5,4127.47 4415,4127.47 4455,4127.47 4491.01,4127.47 5525,4127.62 5525.6,4212.57 5643.92,4224.73 5526.21,4236.97 5625.31,4245.49 5231.07,4343.46 5250.82,4355 5231.07,4366.5 5250.82,4378.62 5231.07,4390.12
VEEL_U: Q4.2 R141.1 | length 74.5
  Top Layer w20: R141.1@1761.5,3545.75 1765.59,3549.84 1765.59,3615.94 Q4.2@1767.4,3617.76
Vg_HS_U: C11.1 D5.1 D6.2 J21.1 Q1.3 Q7.G1 R9.2 R10.2 R12.2 R13.2 R16.2 R17.2 R20.2 R21.2 R23.2 R25.2 TP6.1 | length 1634.2
  Top Layer w20: v1(719.62,1209.35) 719.62,1176.62 R21.2@720.43,1175.81 ; Q1.3@760,1725 760,1732.87 769.78,1742.65 797.24,1742.65 ; C11.1@837.17,2000 837.17,1903.24 797.24,1863.32 J21.1@797.24,1854.53 797.24,1742.65 ; D6.2@897.64,1583.31 880.46,1600.48 R25.2@880.46,1658.45 ; D5.1@977.64,1675 961.09,1658.45 R25.2@880.46,1658.45 ; 797.24,1742.65 880.46,1659.44 R25.2@880.46,1658.45
  Signal Layer 1 w20: v1(719.62,1209.35) 719.62,1776.91 J21.1@797.24,1854.53 ; v1(1400,1755) TP6.1@1400,2050
Vg_HS_V: C41.1 D11.1 D12.2 J4.1 Q2.3 Q7.G3 R47.2 R48.2 R50.2 R51.2 R54.2 R55.2 R58.2 R59.2 R61.2 R63.2 TP17.1 | length 2101.4
  Top Layer w20: v1(2460,1145.86) 2515.9,1145.86 R59.2@2518.07,1148.03 ; Q2.3@2572.4,1744.49 2572.4,1779.29 J4.1@2647.64,1854.53 ; D12.2@2680,1551 2680,1591.74 D11.1@2746.26,1658
  Top Layer w25: J4.1@2647.64,1854.53 2647.64,1855.94 2696.56,1904.85 R63.2@2696.56,2115
  Top Layer w50: J4.1@2647.64,1854.53 2746.26,1755.91 D11.1@2746.26,1658
  Signal Layer 1 w20: v1(2460,1145.86) 2494.7,1180.56 2494.7,1701.59 J4.1@2647.64,1854.53
  Signal Layer 2 w20: J4.1@2647.64,1854.53 2913.11,2120 TP17.1@3000,2120
Vg_HS_W: C71.1 D17.1 D18.2 J25.1 Q3.3 Q7.G5 R85.2 R86.2 R88.2 R89.2 R92.2 R93.2 R96.2 R97.2 R99.2 R101.2 TP27.1 | length 967.3
  Top Layer w20: Q3.3@4498.03,1707.8 J25.1@4498.03,1854.53 4498.03,1936.53 4570,2008.5 4570,2015 4579.25,2024.25 R101.2@4579.25,2076.3 ; TP27.1@4498.03,2224.88 4502.33,2220.58 4502.33,2170.19 4587.52,2085 R101.2@4588.5,2085 ; v1(4657.48,1672.54) 4658.72,1672.54 4849.88,1481.38 4889.88,1481.38 4891.25,1480.01 4891.25,1406.94 R97.2@4890.81,1406.5
Vg_LS_U: C101.1 D23.1 D24.2 J5.1 Q4.3 Q7.G2 R123.2 R124.2 R126.2 R127.2 R132.2 R133.2 R135.2 R136.2 R137.2 R138.2 TP37.1 | length 1267.8
  Top Layer w25: R136.2@1230,3393.19 v1(1230,3496.26) ; D24.2@1495,3458.31 1466.5,3486.81 R138.2@1466.5,3525 1466.5,3704.88 J5.1@1517.72,3756.1 1692.64,3756.1 1730,3718.74 Q4.3@1730,3712.24 1881.5,3712.24 D23.1@1970,3623.74
  Signal Layer 2 w12: J5.1@1517.72,3756.1 1517.72,3962.72 TP37.1@1600,4045
Vg_LS_V: C131.1 D29.1 D30.2 J16.1 Q5.3 Q7.G4 R166.2 R167.2 R169.2 R170.2 R175.2 R176.2 R178.2 R179.2 R180.2 R181.2 TP48.1 | length 845.8
  Top Layer w25: D30.2@2933.31,3780 v1(2933.31,3822.48) ; D29.1@3278.74,3965 3278.79,3964.95 v2(3359.19,3964.95) ; TP48.1@3455,3425 3359.14,3520.86 R181.2@3317.77,3520.91 R181.2@3317.77,3520.91 3317.77,3705.76 J16.1@3368.11,3756.1 3373.55,3761.54 3438.29,3761.54 3456.75,3780 Q5.3@3517.76,3780 3524.25,3780 3525,3779.25 R179.2@3525,3656.5
Vg_LS_W: C161.1 D35.1 D36.2 J13.1 Q6.3 Q7.G6 R209.2 R210.2 R212.2 R213.2 R218.2 R219.2 R221.2 R222.2 R223.2 R224.2 TP59.1 | length 1318.8
  Top Layer w20: R222.2@4746.5,3830 4805,3830 ; D36.2@4805,3896.69 4805,3830 ; v1(4962.81,3730) Q6.3@4922.24,3730 4922.24,3760.16 4852.4,3830 4805,3830
  Top Layer w25: TP59.1@5331.18,3520 R224.2@5176.5,3520 5176.5,3703.17 5218.5,3745.18 J13.1@5218.5,3756.1 D35.1@5436.18,3756.1
  Signal Layer 2 w12: v1(4962.81,3730) 4962.81,3773 5017.34,3827.53 5147.07,3827.53 J13.1@5218.5,3756.1
VHD_U: D1.1 D4.1 J9.1 Q7.C1 R151.2 TP39.1 | length 2595.4
  Top Layer w20: R151.2@2295,1967.91 2297.91,1965 v1(2355,1965)
  Top Layer w50: D1.1@1616.46,1540 1858.33,1540 2283.58,1965.26 2283.58,1967.32 2284.17,1967.91 R151.2@2295,1967.91 ; D4.1@1884.39,1783.23 2029.96,1783.23 J9.1@2064.96,1748.23
  Signal Layer 2 w12: v1(2355,1965) 2610,1965 2890,2245 2890,2560 TP39.1@2525,2925
VHD_V: D7.1 D10.1 J3.1 Q7.C3 R194.2 TP50.1 | length 1913
  Top Layer w50: R194.2@2755,2617.91 2755,2508.98 2983.98,2280 3435,2280 3575,2140 ; TP50.1@3640,2220 3640,2211.88 3575,2146.88 3575,2140 ; D7.1@3725,1671.46 3723.92,1672.54 3723.92,1753.45 ; J3.1@3915.35,1748.23 3729.13,1748.23 3723.92,1753.45 ; 3575,2140 3722.83,1992.17 D10.1@3722.83,1854.53 3723.92,1853.45 3723.92,1753.45
VHD_W: D13.1 D16.1 J8.1 Q7.C5 R237.2 TP61.1 | length 3603.8
  Top Layer w50: v2(4222.09,2233.19) R237.2@4222.09,2297.99 ; D13.1@5367.49,1669.06 5385.01,1686.58 5429.29,1686.58 D16.1@5594.53,1851.81 ; D16.1@5594.53,1869.53 D16.1@5594.53,1851.81 ; J8.1@5765.75,1748.23 5762.81,1751.17 5695.17,1751.17 D16.1@5594.53,1851.81
  Signal Layer 2 w12: 5528.98,1985 5528.98,2308.98 5775,2555 6065,2555 6205,2415 TP61.1@6205,2315
  Signal Layer 2 w50: v2(4222.09,2233.19) 4470.28,1985 5528.98,1985 J8.1@5765.75,1748.23
VrefH_U: C10.1 TP4.1 U1.21 | length 2485
  Top Layer w10: v1(1106.5,985.35) 1106.82,985.68 1106.82,1027.35 U1.21@1107.15,1027.68 1110.22,1030.75 1110.22,1063.61 1190.97,1144.36 C10.1@1190.97,1190.53
  Signal Layer 2 w10: v1(1106.5,985.35) 1106.5,1003.41 1207.74,1104.65 1323.44,1104.65 2378.79,2160 2656.26,2160 TP4.1@2796.26,2300
VrefH_V: C40.1 TP15.1 U2.21 | length 2840
  Top Layer w10: U2.21@2890.73,982.05 2890.73,1030.66 2942.55,1082.48 C40.1@2942.55,1118.5
  Top Layer w12: v1(2890.73,939.72) U2.21@2890.73,982.05
  Signal Layer 2 w12: v1(2890.73,939.72) 3293.43,1342.43 3655,1342.43 3744.36,1431.79 3744.36,2025.64 3109.09,2660.91 TP15.1@3019,2660.91
VrefH_W: C70.1 TP25.1 U3.21 | length 1468.9
  Top Layer w12: U3.21@5212.68,992.05 v1(5212.68,1034.66) 5212.68,1043.27 5279.11,1109.71 C70.1@5279.11,1161.03
  Signal Layer 2 w12: v1(5212.68,1034.66) 5354.52,1176.5 5616.5,1176.5 6030,1590 TP25.1@6030,1815
VrefL_U: C100.1 TP35.1 U4.21 | length 798
  Top Layer w10: U4.21@1056.93,3037.32 1112.45,3037.32 1165.21,2984.57 1214.8,2984.57 C100.1@1228.5,2970.87
  Signal Layer 2 w12: v1(1200.02,2970.9) 1529.44,2970.9 TP35.1@1720,3161.46
VrefL_V: C130.1 TP46.1 U5.21 | length 1090.3
  Top Layer w10: C130.1@2726.61,4187.95 2726.61,4188.94 2761.4,4223.72 2761.4,4237.11 v1(2762.5,4238.21) 2762.5,4239.1 2844.25,4320.86 2844.25,4355 U5.21@2847.32,4358.07
  Signal Layer 2 w10: v1(2762.5,4238.21) 2601.38,4077.09 2601.38,3913.62 TP46.1@2940,3575
VrefL_W: C160.1 TP57.1 U6.21 | length 1733.7
  Top Layer w12: C160.1@5286.57,4185 5286.57,4240.34 5363.24,4317.01 5363.24,4356 U6.21@5365.31,4358.07 ; v1(5360.26,4400.39) 5360.26,4399.38 5363.24,4396.4 5363.24,4361.85 U6.21@5365.31,4359.78
  Signal Layer 2 w12: TP57.1@4105,3845 4646.32,3845 5098.95,4297.64 5247.14,4297.64 5332.18,4382.68 5341.53,4382.68 5359.25,4400.39 v1(5360.26,4400.39)
VSUP_GATE_BIAS: C184.1 C185.1 C186.1 C194.1 C195.1 C196.1 C204.1 C205.1 C206.1 C214.1 C215.1 C216.1 C224.1 C225.1 C226.1 C234.1 C235.1 C236.1 J1.b2 J1.b3 J1.b4 R245.2 R246.2 R253.2 R254.2 R261.2 R262.2 R269.2 R270.2 R277.2 R278.2 R285.2 R286.2 T1.1 T2.1 T3.1 T4.1 T5.1 T6.1 TP65.1 TP67.1 TP69.1 TP71.1 TP73.1 TP75.1 U7.3 U8.3 U9.3 U10.3 U11.3 U12.3 | length 1346.5
  Top Layer w12: R246.2@1830.85,160 1831.5,160.66 1831.5,192.43 v1(1832.16,193.08) ; v1(3552.6,146.34) 3553.32,145.62 3553.32,137 3565.31,125 R262.2@3569.25,125 ; R270.2@3577.87,5215 3581.81,5215 3601.07,5195.74 v1(3601.26,5195.74) ; R286.2@4583.9,5215 4587.83,5215 4607.12,5195.72 4608.77,5195.72 v1(4609.49,5195) ; R278.2@5080,3185 5083.94,3185 5089.75,3179.19 5089.75,3177.56 v1(5103.96,3163.35) ; 5324.9,2893.7 TP73.1@5481.18,2893.7
  Top Layer w20: R254.2@170,2397.99 170,2398.19 171.81,2400 v1(183.21,2400)
  Signal Layer 1 w12: v1(183.21,2400) 260,2400 v1(405,2545) ; v1(3601.26,5195.74) 3765,5032 v1(3765,5017.24) ; v1(4609.49,5195) 4743.5,5060.98 v1(4743.5,5025.65)
  Signal Layer 2 w12: v1(5103.96,3163.35) 5240,3027.3 v1(5240,2960)
  other v1: 3355,343.07 3395,343.07 3435,343.07 1589.71,371.06 1629.71,371.06 1669.71,371.06 405,2585 405,2625 5280,2960 5320,2960 3805,5017.24 3845,5017.24 4783.5,5025.65 4823.5,5025.65
  other v2: 340,4855 390,4855 440,4855 340,4897.83 390,4897.83 440,4897.83
VSUP_PRIM: C241.2 C242.2 J1.b1 R1.1 R2.2 R3.2 R19.2 R39.1 R40.2 R41.2 R57.2 R77.1 R78.2 R79.2 R95.2 R115.1 R116.2 R117.2 R131.2 R158.1 R159.2 R160.2 R174.2 R201.1 R202.2 R203.2 R217.2 R292.2 R294.2 R295.1 U13.14 U14.14 | length 20141.1
  Top Layer w10: U14.14@1624.57,4680.12 1624.57,4739.57 C242.2@1625,4740 ; U13.14@1829.57,4680.12 C241.2@1829.57,4736.81 ; C241.2@1831.38,4740 C241.2@1834.57,4736.81
  Top Layer w20: v1(261.81,3189.37) 261.81,3371.81 305.72,3415.72 460.25,3415.72 464.8,3420.27 ; v2(290,4897.83) J1.b1@290,4950 ; R115.1@464.8,3402.24 464.8,3420.27 ; R117.2@623.35,3476.06 R117.2@621.38,3476.06 495.87,3476.06 v1(464.8,3445) 464.8,3420.27 ; R3.2@700,596.38 698.19,594.57 698.19,583.32 688.39,573.52 688.39,441.61 738.44,391.56 ; v1(787.65,416) 763.22,391.56 738.44,391.56 ; R294.2@889.84,4786.38 890,4786.22 v1(890,4750) ; R295.1@990,4786.38 991.38,4785 v1(1015,4785) ; v1(1017.9,250.74) 818.62,250.74 738.44,330.93 738.44,391.56 ; C242.2@1625,4740 v1(1625,4770) ; C241.2@1831.38,4740 v1(1831.38,4770) ; R41.2@2475,546.38 2475,508.23 2460,493.23 2460,364.61 v1(2470,354.61) ; v1(2490,398.54) R39.1@2523.5,398.54 ; R40.2@2500,353.62 2499.02,354.61 v1(2470,354.61) ; R292.2@2513.62,5030 2515,5031.38 v1(2515,5070.44) ; v1(2728.05,215) 2526.14,215 2470,271.14 v1(2470,354.61) ; R158.1@3242.24,4948.8 v2(3278.74,4948.8) ; R160.2@3260,4798.62 v1(3290,4798.62) ; R79.2@4795,556.38 4753.77,556.4 4720,522.64 4720,425 4795.28,349.72 R77.1@4861.5,349.72 4863.31,347.91 4863.31,318.75 v1(4864.27,317.78) ; R201.1@5743.62,4941.89 v2(5743.62,4971.38) ; R203.2@5796.23,4788.62 v1(5796.23,4827.15)
  Power / GND 2 w12: 216.59,3189.37 v1(261.81,3189.37)
  Power / GND 2 w20: v1(1015,4785) 980,4750 v1(890,4750) 840,4800 840,4950 ; v1(1017.9,250.74) 1017.9,200 ; v1(1625,4770) 1625,4950 ; v1(1831.38,4770) 1831.38,4947.58 1833.8,4950 ; v1(2515,5070.44) 2510.45,5074.99 2510.45,5099.78 ; v1(2728.05,215) 2728.05,103.9 2731.18,100.77 ; v2(3278.74,4948.8) 3278.74,4983.59 ; v1(3290,4798.62) 3320.98,4829.6 3320.98,4971.88 3309.26,4983.59 3278.74,4983.59 ; v1(4864.27,317.78) 4864.27,275.45 ; v1(5048,280) 4868.82,280 4864.27,275.45 ; v2(5743.62,4971.38) 5743.62,5003.2 ; v1(5796.23,4827.15) 5796.23,4989.47 5782.5,5003.2 5743.62,5003.2 ; 840,4950 1625,4950 ; 840,4950 342.17,4950 v2(290,4897.83) 160,4767.83 160,4506.38 215.95,4450.43 215.95,3153.28 215.95,2500.23 237.87,2478.3 237.87,1825.25 151.57,1738.95 151.57,843.43 795,200 1017.9,200 ; 1017.9,200 1638.62,200 1737.86,100.77 2731.18,100.77 ; 1625,4950 1833.8,4950 ; 1833.8,4950 1975.22,4950 2125,5099.78 2510.45,5099.78 ; 2510.45,5099.78 v1(3055,5099.78) 3197.34,5099.78 3278.74,5018.39 ; 2731.18,100.77 4789.35,100.77 4864.27,175.69 4864.27,275.45 ; 3278.74,4983.59 3278.74,5018.39 ; 3278.74,5018.39 3419.12,5158.77 4000,5158.77 4098.77,5060 4459.89,5060 4499.89,5100 v1(5560.96,5100) 5678.64,5100 5743.62,5035.02 5743.62,5003.2
  Bottom Layer w12: R131.2@235,3162.56 v1(261.81,3189.37)
  Bottom Layer w20: R131.2@235,3158.62 R131.2@235,3162.56 ; R116.2@378.62,3389.39 380.43,3391.2 384.37,3391.2 437.48,3444.31 464.11,3444.31 v1(464.8,3445) ; v1(1017.9,250.74) 1067.52,250.74 R19.2@1068.27,250 ; v1(2728.05,215) R57.2@2762.82,215 ; R174.2@3013.43,5100 3054.78,5100 v1(3055,5099.78) ; R159.2@3243.62,5018.62 3247.56,5018.62 3278.05,4988.13 3278.05,4949.5 v2(3278.74,4948.8) ; v1(4864.27,317.78) R78.2@4864.27,371.38 ; v1(5048,280) R95.2@5091.38,280 ; R217.2@5526.93,5100 v1(5560.96,5100) ; R202.2@5695.06,4971.38 v2(5743.62,4971.38)
pads on no net: J1. J1.1 J1.2 J1.3 J1.4 J1.b5 J14.1 J20.1 J26.1 Q7. Q7.C2 Q7.C4 Q7.C6 T1.2 T1.3 T2.2 T2.3 T3.2 T3.3 T4.2 T4.3 T5.2 T5.3 T6.2 T6.3 U7.9@1824,356.93 U7.9@1883.44,356.93 U8.9@390,2328.9 U8.9@390,2388.35 U9.9@3604.65,313.94 U9.9@3664.09,313.94 U10.9@3540.28,5035 U10.9@3599.72,5035 U11.9@5023.03,2989.8 U11.9@5082.48,2989.8 U12.9@4530.55,5035 U12.9@4590,5035 U13.11

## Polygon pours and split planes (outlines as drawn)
VCC2H_V on Top Layer "VCC2H_V_L01_P071" (solid, pour order 71): 2792.62,1104.57 2792.62,1105.94 2772.62,1125.94 2772.62,1168.26 2834.07,1168.26 2886.81,1115.52 2886.81,1069.33 2840.08,1022.6 2823.99,1022.6 2823.99,1030.87 2792.03,1062.83
GND2H_W on Top Layer "GND2H_W_L01_P121" (solid, pour order 121): 5278.5,1096.97 5286.99,1105.46 5286.99,1140 5715,1140 5715,1261.52 5634,1342.52 5361,1342.52 5361,1453.19 5269.19,1545 5165.04,1545 5094.57,1474.53 5094.57,1096.97
VEE2L_U on Top Layer "VEE2L_U_L01_P161" (solid, pour order 161): 1112.67,2897.78 1112.67,2950.27 1020,2950.27 1020,2897.78
GND on Top Layer "GND_L01_P160" (solid, remove dead copper, pour order 160): 36 vertices, not listed, extent -90.44,5.26 6324.56,5315.26
GND on Top Layer "GND_L01_P157" (solid, pour order 157): 596.65,3359.5 596.65,3433.07 571.42,3458.31 503.31,3458.31 486.46,3441.46 486.46,3363.5 493.63,3356.33 596.77,3356.33
GND on Top Layer "GND_L01_P156" (solid, pour order 156): 5666.18,4813.54 5784.49,4813.54 5796.23,4825.28 5796.23,4897.83 5779.02,4915.05 5666.38,4915.05
GND on Top Layer "GND_L01_P155" (solid, pour order 155): 4838.87,525.6 4838.87,396.18 4836.25,393.56 4766.68,393.56 4726.25,434 4726.25,525.6
VSUP_GATE_BIAS on Top Layer "VSUP_GATE_BIAS_L01_P154" (solid, pour order 154): 320,4897.83 320.59,4898.43 320.59,4975.59 459.41,4975.59 460,4975 460,4843.62 450,4833.62 331.38,4833.62 320,4845
GND on Top Layer "GND_L01_P153" (solid, pour order 153): 715.38,459.7 702.08,473.01 702.08,564.64 708.23,570.79 800.87,570.79 806.53,565.12 806.53,460.16
VSUP_PRIM on Top Layer "VSUP_PRIM_L01_P152" (solid, pour order 152): 730.44,399.56 730.44,444.65 747.44,461.65 781.73,461.65 797.13,446.26 797.13,372.12 757.88,372.12
DesatL_W on Top Layer "DESATL_W_L01_P151" (solid, pour order 151): 5107,3987 5120,4000 5207.45,4000 5238.75,3968.7 5238.75,3903.73 5224.07,3889.04 5118.94,3889.04 5107,3900.98
GND2H_V on Top Layer "GND2H_V_L01_P072" (solid, remove dead copper, pour order 72): 2780.79,1469.53 2926.26,1615 3797.56,1615 3828.84,1583.72 3828.84,945 2955.35,945 2780.79,1119.57
VrefL_U on Top Layer "VREFL_U_L01_P146" (solid, pour order 146): 1247,2942.32 1200.44,2942.32 1160.55,2982.21 1167.91,2989.57 1246.65,2989.57
GND on Top Layer "GND_L01_P125" (solid, pour order 125): 4497.33,4989.01 4386.96,5099.37 4386.96,5250.39 4804.61,5250.39 4854.52,5200.48 4854.52,4989.47
GND on Top Layer "GND_L01_P124" (solid, pour order 124): 3508.07,4982.05 3397.7,5092.41 3397.7,5243.43 3815.35,5243.43 3865.26,5193.52 3865.26,4982.51
NetC121_1 on Top Layer "NETC121_1_L01_P123" (solid, pour order 123): 3055.02,4774.68 3055,4774.7 3055,4848 3167.61,4960.61 3215,4960.61 3215,4856.82 3181.23,4823.06 3099.22,4823.06 3059.92,4783.76
GND on Top Layer "GND_L01_P122" (solid, pour order 122): 78.74,2655 397.01,2655 397.01,2528.81 474.65,2451.17 474.65,2275.51 249.32,2050.19 78.74,2050.19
